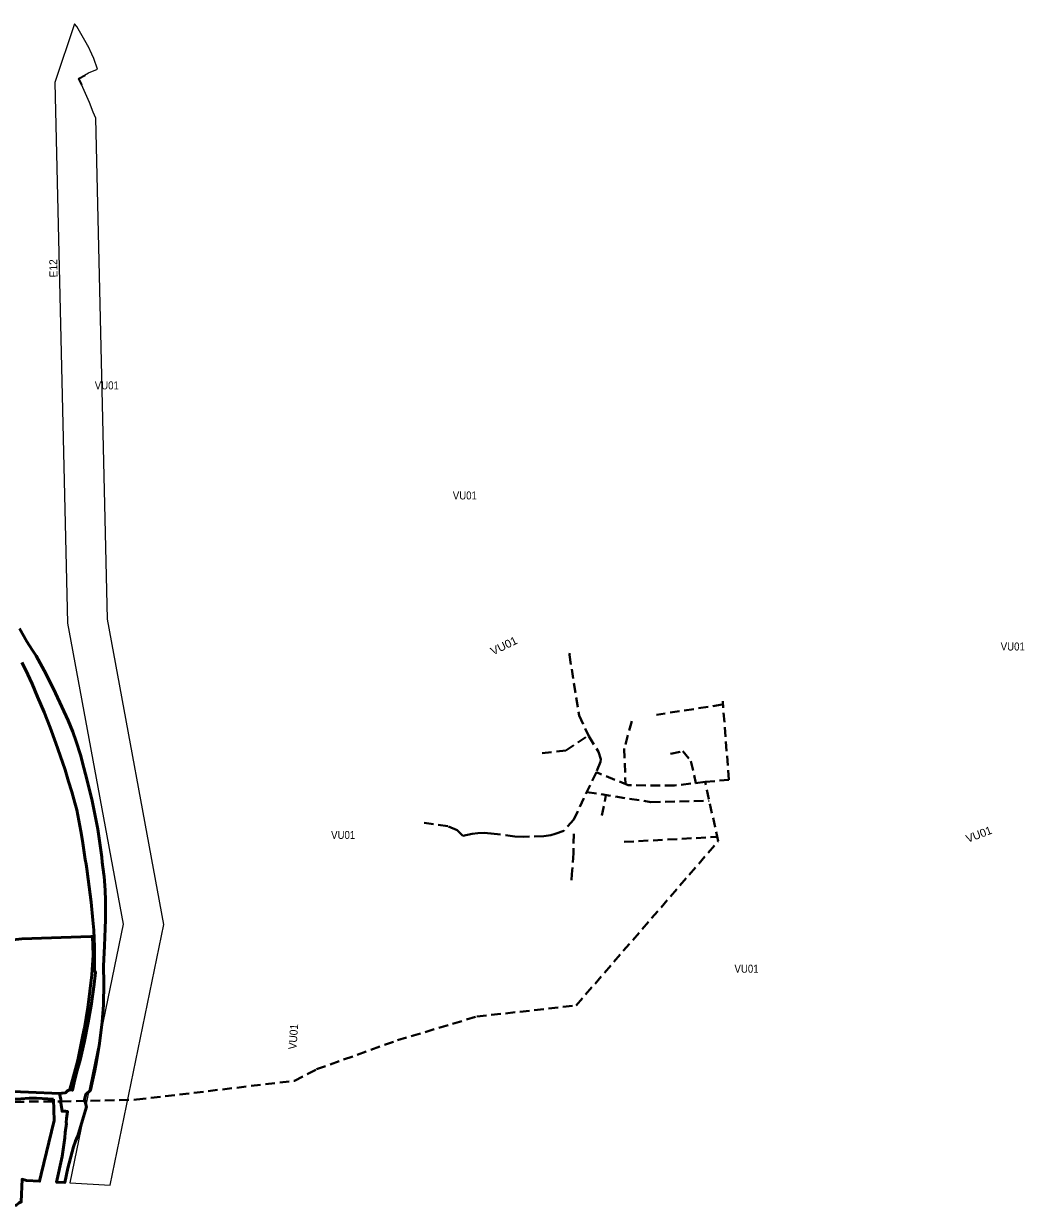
# Model space of a CAD drawing. Extents: x -650145 to -642675, y -1074338 to -1066803.
# Drawn here: x -645175 to -642675, y -1071042 to -1068085 of the extents above; entities that cross this region are included whole.
import ezdxf

# ---------------------------------------------------------------- set-up
doc = ezdxf.new("R2010")
doc.units = 0
doc.header["$LTSCALE"] = 8
doc.linetypes.add('MEDIUM_DASHED', pattern=[4.5, 3, -1.5])
for name, color, linetype, lineweight in [('12', 7, 'MEDIUM_DASHED', 40), ('13', 7, 'MEDIUM_DASHED', 40), ('15', 7, 'Continuous', 13), ('45', 7, 'Continuous', 53), ('53', 7, 'Continuous', 53)]:
    doc.layers.add(name, color=color, linetype=linetype, lineweight=lineweight)
doc.layers.add('17', color=7, linetype='Continuous')
doc.layers.add('2', color=7, linetype='Continuous')

msp = doc.modelspace()

# ---------------------------------------------------------------- linework, layer by layer
at = {"layer": '12'}
for p, q in [((-643429.636, -1069786.459), (-643594.181, -1069811.599)), ((-643730.467, -1070063.614), (-643720.12, -1070012.253)), ((-643674.528, -1070129.34), (-643442.257, -1070116.937))]:
    msp.add_line(p, q, dxfattribs=at)
for points in [[(-643810.627, -1069657.665), (-643811.385, -1069662.021), (-643787.529, -1069813.369), (-643763.019, -1069865.538), (-643739.057, -1069904.105), (-643733.398, -1069922.453), (-643733.672, -1069929.3), (-643744.205, -1069955.268), (-643800.43, -1070073.069), (-643825.501, -1070101.354), (-643846.88, -1070109.266), (-643858.108, -1070112.46), (-643875.543, -1070114.925), (-643927.411, -1070116.568), (-643947.688, -1070115.858), (-644007.981, -1070107.962), (-644024.686, -1070106.729), (-644040.027, -1070107.201), (-644054.663, -1070109.432), (-644077.983, -1070114.354), (-644091.49, -1070099.721), (-644115.344, -1070090.018), (-644174.372, -1070081.528)], [(-644443.224, -1070697.577), (-644241.161, -1070625.072), (-644042.664, -1070565.642), (-643794.576, -1070538.041), (-643439.868, -1070127.812), (-643472.434, -1069979.54), (-643413.032, -1069974.132), (-643428.496, -1069777.693)], [(-643655.213, -1069827.906), (-643674.851, -1069896.398), (-643671.269, -1069984.982)], [(-643879.717, -1069908.04), (-643820.566, -1069900.574), (-643763.8, -1069863.876)], [(-643558.728, -1069909.08), (-643528.249, -1069902.841), (-643508.036, -1069927.391), (-643495.611, -1069982.269)], [(-643472.434, -1069979.54), (-643548.771, -1069988.527), (-643664.391, -1069987.784), (-643744.205, -1069955.268)], [(-643767.825, -1070004.757), (-643608.243, -1070029.834), (-643462.149, -1070026.369)], [(-643800.52, -1070109.14), (-643801.571, -1070157.278), (-643805.1, -1070210.207), (-643806.511, -1070225.027)]]:
    msp.add_lwpolyline(points, dxfattribs=at)
at = {"layer": '13'}
msp.add_lwpolyline([(-645445.374, -1070804.496), (-645420.722, -1070830.204), (-645305.382, -1070779.425), (-645079.923, -1070777.683), (-644892.766, -1070773.328), (-644498.43, -1070726.295), (-644498.43, -1070726.295), (-644443.224, -1070697.577)], dxfattribs=at)
at = {"layer": '15'}
for points in [[(-645047.446, -1068085.007), (-645096.974, -1068231.922), (-645065.08, -1069583.124), (-644926.299, -1070334.854)], [(-644958.761, -1070986.696), (-644824.411, -1070335.926), (-644965.296, -1069572.802), (-644994.849, -1068320.753), (-645000.93, -1068306.11), (-645010.65, -1068282), (-645036.69, -1068221.92), (-645012.64, -1068208.23), (-644990.43, -1068198.75), (-644999.74, -1068171.88), (-645004.64, -1068161.3), (-645014.09, -1068140.85), (-645015.38, -1068138.59), (-645041.75, -1068092.48), (-645047.446, -1068085.007)], [(-644926.299, -1070334.854), (-645059.782, -1070981.425), (-645058.66, -1070981.49), (-645058.472, -1070980.896), (-644958.761, -1070986.696)]]:
    msp.add_lwpolyline(points, dxfattribs=at)
at = {"layer": '15', "lineweight": 35}
msp.add_lwpolyline([(-645029.39, -1068238.047), (-645036.69, -1068221.92), (-645021.142, -1068213.582)], dxfattribs=at)
at = {"layer": '45'}
msp.add_lwpolyline([(-645179.12, -1069681.3), (-645170.3, -1069698.91), (-645153.44, -1069734.71), (-645140.27, -1069766.68), (-645123.84, -1069805.38), (-645108.74, -1069843.58), (-645094.42, -1069882.65), (-645083.31, -1069913.37), (-645071.53, -1069948.89), (-645062.57, -1069978.46), (-645054.73, -1070004.56), (-645047.28, -1070031.83), (-645042.27, -1070049.23), (-645032.21, -1070102.73), (-645027.49, -1070126.56), (-645021.14, -1070173.07), (-645018.56, -1070184.92), (-645016.92, -1070196.32), (-645013.51, -1070222.04), (-645005.98, -1070280.14), (-645001.81, -1070324.58), (-644999.47, -1070349.63), (-644997.87, -1070391.16), (-644998.17, -1070450.59), (-644995.14, -1070455.72), (-644998.92, -1070484.58), (-645006.44, -1070538.78), (-645014.07, -1070580.72), (-645022.64, -1070626.93), (-645033.53, -1070674.55), (-645041, -1070700.44), (-645046.63, -1070722.77), (-645053.21, -1070749.75), (-645060.46, -1070749.1), (-645065.17, -1070751.39), (-645070.3, -1070755.92), (-645085.58, -1070758.04), (-645081.75, -1070772.79), (-645081.85, -1070781.59), (-645081.13, -1070786.56), (-645078.85, -1070802.46), (-645070.2, -1070802.33), (-645065.01, -1070803.22), (-645068.07, -1070820.37), (-645068.52, -1070830.52), (-645068.07, -1070832.72), (-645071.18, -1070855.63), (-645071.77, -1070868.73), (-645078.23, -1070915.65), (-645092.67, -1070979.52), (-645071.99, -1070980.72), (-645064.39, -1070944.7), (-645050.47, -1070891.48), (-645045.74, -1070877.19), (-645043, -1070871.35), (-645039.25, -1070863.33), (-645028.25, -1070824.83), (-645018.18, -1070791.34), (-645023.25, -1070772.62), (-645019.57, -1070760.07), (-645007.68, -1070749.5), (-645001.71, -1070723.39), (-644997.14, -1070700.88), (-644992.6, -1070677.92), (-644985.04, -1070633.43), (-644978.44, -1070578.56), (-644975.05, -1070536.16), (-644974.44, -1070482.48), (-644975.29, -1070440.14), (-644972.48, -1070389.15), (-644971.37, -1070345.98), (-644970.61, -1070323.44), (-644970.36, -1070275.49), (-644971.47, -1070250.14), (-644974, -1070216.2), (-644974.49, -1070210.98), (-644978.49, -1070180.05), (-644979.57, -1070167.9), (-644984.21, -1070132.81), (-644989.62, -1070097.79), (-644996.88, -1070059.73), (-645004.02, -1070026.44), (-645016.01, -1069976.23), (-645024.45, -1069944.43), (-645032.85, -1069912.07), (-645043.5, -1069878.37), (-645051.78, -1069854.2), (-645063.26, -1069825.99), (-645095.1, -1069757.62), (-645118.98, -1069710.08), (-645143.56, -1069664.05), (-645153.33, -1069649.24), (-645166.67, -1069629), (-645184.88, -1069596.58)], dxfattribs=at)
at = {"layer": '53'}
for points in [[(-645442.834, -1070659.455), (-645449.82, -1070592.72), (-645448.36, -1070563), (-645454.02, -1070501.52), (-645458.46, -1070478.86), (-645455.09, -1070479.21), (-645451.226, -1070466.394), (-645440.61, -1070469.53), (-645404.4, -1070435.88), (-645404.34, -1070433.93), (-645408.66, -1070414.62), (-645409.38, -1070411.41), (-645414.65, -1070395.37), (-645326.62, -1070388.32), (-645179.26, -1070371.74), (-645006.86, -1070365.38), (-645003.102, -1070365.432), (-645003.03, -1070365.427), (-645001.312, -1070412.099), (-645004.327, -1070461.264), (-645014.277, -1070543.11), (-645023.048, -1070595.033), (-645023.346, -1070596.478)], [(-645023.346, -1070596.478), (-645028.384, -1070620.876), (-645039.574, -1070675.065), (-645045.493, -1070696.321), (-645059.308, -1070747.712), (-645059.421, -1070749.039), (-645060.46, -1070749.1), (-645065.17, -1070751.39), (-645070.3, -1070755.92), (-645079.38, -1070756.91), (-645085.58, -1070758.04), (-645163.06, -1070754.64), (-645202.96, -1070752.89), (-645275.236, -1070750.954)], [(-645100.268, -1070771.946), (-645143, -1070770), (-645161, -1070770), (-645182, -1070771), (-645303, -1070774), (-645351, -1070800), (-645400.05, -1070819.84), (-645406.09, -1070822.34), (-645409.52, -1070823.76), (-645418.67, -1070827.72), (-645421.09, -1070827.89), (-645433.49, -1070828.76), (-645452.31, -1070825.52), (-645455.184, -1070825.042)], [(-645130.749, -1070959.561), (-645098.438, -1070825.558), (-645100.268, -1070771.946)], [(-645495.87, -1071017.81), (-645475.01, -1071020.72), (-645426.38, -1071032.8), (-645361.54, -1071041.54), (-645255.93, -1071042.36), (-645203.66, -1071038.81), (-645193.24, -1071037.31), (-645186.18, -1071030.83), (-645180.72, -1071028.86), (-645178.73, -1070972.35), (-645167.47, -1070975.2), (-645134.973, -1070977.077), (-645134.973, -1070977.077), (-645130.749, -1070959.561)]]:
    msp.add_lwpolyline(points, dxfattribs=at)

# ---------------------------------------------------------------- texts
at = {"layer": '17', "width": 0.95}
msp.add_text('E12', height=20, rotation=90.939, dxfattribs=at).set_placement((-645090.224, -1068718.688))
at = {"layer": '2', "width": 0.9}
for p in [(-644997.156, -1068998.703), (-644102.761, -1069273.709), (-642734.104, -1069651.125), (-644406.791, -1070121.981), (-643399.108, -1070456.171)]:
    msp.add_text('VU01', height=20, dxfattribs=at).set_placement(p)
at = {"layer": '2'}
for rotation, width, p in [(25.964, 1.05, (-644002.392, -1069663.63)), (85.874, 0.95, (-644493.521, -1070648.37))]:
    msp.add_text('VU01', height=20, rotation=rotation, dxfattribs=dict(at, width=width)).set_placement(p)
msp.add_text('VU01', height=20, rotation=20.965, dxfattribs=at).set_placement((-642816.364, -1070131.907))

doc.saveas('drawing.dxf')
